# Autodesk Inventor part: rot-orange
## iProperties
Created: 2004-10
Part Number: rot-orange
Document SubType Name: Modeling
Designer: sahrens
Manufacturer: Standard
Standards Organization: Custom
Author: sahrens
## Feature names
1. Extrusion1
2. Rundung2 [Fillet]
